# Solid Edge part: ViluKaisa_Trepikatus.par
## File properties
Author: kaisa
Template: Iso Metric Part.par
Last saved by: kaisa
Revision: 6
Application: Solid Edge
Density: 600.000 kg/m^3
Accuracy: 0.990
Username: kaisa
Material: Wood, Mahogany
Face Style: Tan
Fill Style: Wood (Radial)
Virtual Style: Wood (Radial)
Grouping: Non-metals\Woods
LibraryName: Materials
Coef. of Thermal Exp: 0.0
Thermal Conductivity: 0.0
Specific Heat: 0.0
Modulus of Elasticity: 0.0
Poisson's Ratio: 0.428
Yield Stress: 0.0
Ultimate Stress: 0.0
Elongation: 0.0
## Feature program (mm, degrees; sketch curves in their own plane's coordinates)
sketch for "unnamed Protrusion 1" plane through (0, 0, 0) normal (0, 0, 1) x-axis (1, 0, 0)
  line (-20.4133, 35.3589) -> (-20.4133, -35.3589)
  line (-20.4133, -35.3589) -> (20.4133, -35.3589)
  line (20.4133, -35.3589) -> (20.4133, 35.3589)
  line (20.4133, 35.3589) -> (-20.4133, 35.3589)
extrude "unnamed Protrusion 1" add finite 50 along +normal
draft "Draft_1"  Angles1 = 3 deg
chamfer "Chamfer_1" setback 4
thinwall "Thinwall_1"  Thickness = 3 mm
sketch for "unnamed Protrusion 2" #1 plane through (-22.8268, 0, 23.0551) normal (-0.99863, 0, 0.052336) x-axis (0, -1, 0)
  line (0, 0) -> (0, 0)
  line (0, 0) -> (0, 0)
  line (0, 0) -> (0, 0)
  line (0, 0) -> (0, 0)
sketch for "unnamed Protrusion 2" #2 plane through (-22.8268, 0, 23.0551) normal (-0.99863, 0, 0.052336) x-axis (0, -1, 0)
sketch for "unnamed Protrusion 2" #3 plane through (-22.8268, 0, 23.0551) normal (-0.99863, 0, 0.052336) x-axis (0, -1, 0)
sketch for "unnamed Protrusion 2" #4 plane through (-22.8268, 0, 23.0551) normal (-0.99863, 0, 0.052336) x-axis (0, -1, 0)
sketch for "unnamed Protrusion 2" #5 plane through (-22.8268, 0, 23.0551) normal (-0.99863, 0, 0.052336) x-axis (0, -1, 0)
sketch for "unnamed Protrusion 2" #6 plane through (-22.8268, 0, 23.0551) normal (-0.99863, 0, 0.052336) x-axis (0, -1, 0)
sketch for "unnamed Protrusion 2" #7 plane through (-22.8268, 0, 23.0551) normal (-0.99863, 0, 0.052336) x-axis (0, -1, 0)
sketch for "unnamed Protrusion 2" #8 plane through (-22.8268, 0, 23.0551) normal (-0.99863, 0, 0.052336) x-axis (0, -1, 0)
sketch for "unnamed Protrusion 2" #9 plane through (-22.8268, 0, 23.0551) normal (-0.99863, 0, 0.052336) x-axis (0, -1, 0)
sketch for "unnamed Protrusion 2" #10 plane through (-22.8268, 0, 23.0551) normal (-0.99863, 0, 0.052336) x-axis (0, -1, 0)
sketch for "unnamed Protrusion 2" #11 plane through (-22.8268, 0, 23.0551) normal (-0.99863, 0, 0.052336) x-axis (0, -1, 0)
sketch for "unnamed Protrusion 2" #12 plane through (-22.8268, 0, 23.0551) normal (-0.99863, 0, 0.052336) x-axis (0, -1, 0)
sketch for "unnamed Protrusion 2" #13 plane through (-22.8268, 0, 23.0551) normal (-0.99863, 0, 0.052336) x-axis (0, -1, 0)
sketch for "unnamed Protrusion 2" #14 plane through (-22.8268, 0, 23.0551) normal (-0.99863, 0, 0.052336) x-axis (0, -1, 0)
sketch for "unnamed Protrusion 2" #15 plane through (-22.8268, 0, 23.0551) normal (-0.99863, 0, 0.052336) x-axis (0, -1, 0)
extrude "unnamed Protrusion 2" add along -normal
Other named dimensions: "OffsetSurface_1": Distance = 1 mm | "OffsetSurface_2": Distance = 0.1 mm
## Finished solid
Body 1: sheet body, 1 face, 4 edges, 4 vertices.
  Faces by surface: plane 1
  Edges by curve: line 4
Body 2: sheet body, 1 face, 4 edges, 4 vertices.
  Faces by surface: plane 1
  Edges by curve: line 4
Body 3: solid body, 775 faces, 2241 edges, 1490 vertices, 12 separate solids.
  Faces by surface: swept 391, plane 302, cylinder 82
  Edges by curve: line 1295, spline 744, circle 164, intersection 38
Bounding box of the edges (mm; curved faces can reach further): 47.066 x 75.959 x 50.000, from (-24.0323, -37.9793, 0) to (23.0337, 37.9793, 50).
Cylindrical faces by radius (mm): R0.0759 x1, R0.0771 x2, R0.0831 x1, R0.0975 x1, R0.1063 x1, R0.1142 x1, R0.1214 x1, R0.1384 x1, R0.1406 x1, R0.1437 x1, R0.1473 x1, R0.1579 x1, R0.1651 x1, R0.1656 x1, R0.1895 x1, R0.1954 x1, R0.2028 x1, R0.204 x1, R0.2082 x1, R0.2088 x1, R0.2157 x1, R0.2217 x1, R0.2575 x1, R0.2582 x1, R0.2663 x1, R0.2747 x1, R0.2906 x1, R0.2915 x1, R0.2988 x1, R0.3017 x1, R0.3364 x1, R0.3369 x1, R0.3513 x1, R0.3599 x1, R0.3693 x1, R0.3805 x1, R0.3907 x1, R0.4041 x1, R0.4165 x1, R0.427 x1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
Planar faces by outward normal: +y 3, +z 1, -y 10, -z 2, oblique 286
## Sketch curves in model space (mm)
line (20.4133, -35.3589, 0) -> (20.4133, 35.3589, 0)
line (20.4133, 35.3589, 0) -> (-20.4133, 35.3589, 0)
line (-20.4133, 35.3589, 0) -> (-20.4133, -35.3589, 0)
line (-20.4133, -35.3589, 0) -> (20.4133, -35.3589, 0)
spline (-22.2942, -23.682, 33.2179) -> (-22.292, -23.7228, 33.2594) -> (-22.2898, -23.7928, 33.3009)
spline (-22.2991, -23.5267, 33.1238) -> (-22.2964, -23.6272, 33.175) -> (-22.2942, -23.682, 33.2179)
spline (-22.3037, -23.4103, 33.0352) -> (-22.3014, -23.4685, 33.0795) -> (-22.2991, -23.5267, 33.1238)
spline (-22.313, -23.0943, 32.858) -> (-22.3094, -23.2232, 32.9279) -> (-22.3037, -23.4103, 33.0352)
spline (-22.322, -22.8836, 32.6864) -> (-22.3179, -22.9963, 32.7657) -> (-22.313, -23.0943, 32.858)
spline (-22.3238, -22.8226, 32.6532) -> (-22.3233, -22.8531, 32.6615) -> (-22.322, -22.8836, 32.6864)
spline (-22.3284, -22.6674, 32.5646) -> (-22.3261, -22.7448, 32.6094) -> (-22.3238, -22.8226, 32.6532)
spline (-22.3307, -22.5732, 32.5203) -> (-22.3296, -22.6099, 32.5424) -> (-22.3284, -22.6674, 32.5646)
spline (-22.2985, -22.4456, 33.1348) -> (-22.3306, -22.1165, 32.5224) -> (-22.3307, -22.5732, 32.5203)
spline (-22.2933, -22.4844, 33.2345) -> (-22.2959, -22.465, 33.1847) -> (-22.2985, -22.4456, 33.1348)
spline (-22.2863, -22.6341, 33.3674) -> (-22.2912, -22.5219, 33.2739) -> (-22.2933, -22.4844, 33.2345)
spline (-22.2759, -22.806, 33.5667) -> (-22.2797, -22.6951, 33.494) -> (-22.2863, -22.6341, 33.3674)
spline (-22.2631, -23.0721, 33.8103) -> (-22.2685, -22.989, 33.7072) -> (-22.2759, -22.806, 33.5667)
spline (-22.2428, -24.0257, 34.1978) -> (-22.2503, -23.5272, 34.0542) -> (-22.2631, -23.0721, 33.8103)
spline (-22.244, -24.1421, 34.1757) -> (-22.2434, -24.0839, 34.1868) -> (-22.2428, -24.0257, 34.1978)
spline (-22.2434, -24.2142, 34.1868) -> (-22.2437, -24.1781, 34.1812) -> (-22.244, -24.1421, 34.1757)
spline (-22.2454, -24.2918, 34.148) -> (-22.2444, -24.253, 34.1674) -> (-22.2434, -24.2142, 34.1868)
spline (-22.2448, -24.4027, 34.1591) -> (-22.2451, -24.3472, 34.1535) -> (-22.2454, -24.2918, 34.148)
spline (-22.2454, -24.5025, 34.148) -> (-22.2451, -24.4526, 34.1535) -> (-22.2448, -24.4027, 34.1591)
spline (-22.244, -24.5468, 34.1757) -> (-22.2447, -24.5246, 34.1618) -> (-22.2454, -24.5025, 34.148)
spline (-22.273, -24.07, 33.622) -> (-22.2594, -24.3533, 33.8818) -> (-22.244, -24.5468, 34.1757)
spline (-22.2898, -23.7928, 33.3009) -> (-22.2799, -23.9314, 33.4892) -> (-22.273, -24.07, 33.622)
spline (-22.2976, -25.5558, 33.1514) -> (-22.2934, -25.6147, 33.2317) -> (-22.2901, -25.6778, 33.2954)
spline (-22.2988, -25.5004, 33.1293) -> (-22.2982, -25.5281, 33.1404) -> (-22.2976, -25.5558, 33.1514)
spline (-22.3127, -25.1234, 32.8636) -> (-22.3049, -25.384, 33.013) -> (-22.2988, -25.5004, 33.1293)
spline (-22.3052, -25.0846, 33.0075) -> (-22.31, -25.0936, 32.9148) -> (-22.3127, -25.1234, 32.8636)
spline (-22.2971, -25.1068, 33.1625) -> (-22.3011, -25.0957, 33.085) -> (-22.3052, -25.0846, 33.0075)
spline (-22.2785, -25.1899, 33.5169) -> (-22.2875, -25.1019, 33.345) -> (-22.2971, -25.1068, 33.1625)
spline (-22.2611, -25.3063, 33.849) -> (-22.2698, -25.2472, 33.6836) -> (-22.2785, -25.1899, 33.5169)
spline (-22.2016, -24.1865, 34.984) -> (-22.2122, -25.0544, 34.7816) -> (-22.2611, -25.3063, 33.849)
spline (-22.2016, -24.1754, 34.984) -> (-22.2016, -24.1809, 34.984) -> (-22.2016, -24.1865, 34.984)
spline (-22.1993, -24.0312, 35.0283) -> (-22.1996, -24.0897, 35.023) -> (-22.2016, -24.1754, 34.984)
spline (-22.2564, -22.2405, 33.9376) -> (-22.2213, -23.0626, 34.6077) -> (-22.1993, -24.0312, 35.0283)
spline (-22.2814, -21.8303, 33.4615) -> (-22.2679, -22.0162, 33.7191) -> (-22.2564, -22.2405, 33.9376)
spline (-22.2852, -21.7748, 33.3895) -> (-22.2833, -21.8025, 33.4255) -> (-22.2814, -21.8303, 33.4615)
spline (-22.3119, -21.5531, 32.8802) -> (-22.2991, -21.5869, 33.1233) -> (-22.2852, -21.7748, 33.3895)
spline (-22.3272, -21.4533, 32.5867) -> (-22.3175, -21.4447, 32.7719) -> (-22.3119, -21.5531, 32.8802)
spline (-22.3435, -21.4921, 32.2767) -> (-22.3356, -21.4457, 32.4271) -> (-22.3272, -21.4533, 32.5867)
spline (-22.3557, -21.5531, 32.0442) -> (-22.3496, -21.5226, 32.1604) -> (-22.3435, -21.4921, 32.2767)
spline (-22.3551, -22.7727, 32.0552) -> (-22.3706, -22.0696, 31.7594) -> (-22.3557, -21.5531, 32.0442)
spline (-22.3533, -22.8115, 32.0885) -> (-22.3542, -22.7921, 32.0719) -> (-22.3551, -22.7727, 32.0552)
spline (-22.3162, -23.6321, 32.7971) -> (-22.3368, -23.2574, 32.4052) -> (-22.3533, -22.8115, 32.0885)
spline (-22.3168, -23.7429, 32.786) -> (-22.3165, -23.6875, 32.7916) -> (-22.3162, -23.6321, 32.7971)
spline (-22.3139, -23.7984, 32.8414) -> (-22.3153, -23.7707, 32.8137) -> (-22.3168, -23.7429, 32.786)
spline (-22.3069, -23.9869, 32.9743) -> (-22.3104, -23.9037, 32.9078) -> (-22.3139, -23.7984, 32.8414)
spline (-22.3052, -24.009, 33.0075) -> (-22.3061, -23.998, 32.9909) -> (-22.3069, -23.9869, 32.9743)
spline (-22.2997, -24.1255, 33.1127) -> (-22.3026, -24.0735, 33.0559) -> (-22.3052, -24.009, 33.0075)
spline (-22.2924, -24.1975, 33.2511) -> (-22.2952, -24.1574, 33.1985) -> (-22.2997, -24.1255, 33.1127)
spline (-22.2863, -24.4193, 33.3674) -> (-22.2904, -24.316, 33.2903) -> (-22.2924, -24.1975, 33.2511)
spline (-22.2884, -24.4415, 33.3286) -> (-22.287, -24.4366, 33.3542) -> (-22.2863, -24.4193, 33.3674)
spline (-22.3029, -24.4082, 33.0518) -> (-22.2956, -24.4249, 33.1902) -> (-22.2884, -24.4415, 33.3286)
spline (-22.3058, -24.4193, 32.9964) -> (-22.3042, -24.4117, 33.0262) -> (-22.3029, -24.4082, 33.0518)
spline (-22.3156, -24.4359, 32.8082) -> (-22.3101, -24.429, 32.9141) -> (-22.3058, -24.4193, 32.9964)
spline (-22.3185, -24.4637, 32.7528) -> (-22.3172, -24.4581, 32.7784) -> (-22.3156, -24.4359, 32.8082)
spline (-22.3243, -24.4415, 32.6421) -> (-22.3214, -24.4526, 32.6975) -> (-22.3185, -24.4637, 32.7528)
spline (-22.3391, -24.5524, 32.3597) -> (-22.3322, -24.4791, 32.4919) -> (-22.3243, -24.4415, 32.6421)
spline (-22.3429, -24.5912, 32.2878) -> (-22.3411, -24.5635, 32.3217) -> (-22.3391, -24.5524, 32.3597)
spline (-22.3383, -25.4228, 32.3764) -> (-22.3481, -24.9709, 32.1882) -> (-22.3429, -24.5912, 32.2878)
spline (-22.3351, -25.4339, 32.4373) -> (-22.3367, -25.4283, 32.4068) -> (-22.3383, -25.4228, 32.3764)
spline (-22.3325, -25.5669, 32.4871) -> (-22.334, -25.5045, 32.458) -> (-22.3351, -25.4339, 32.4373)
spline (-22.3145, -26.0215, 32.8303) -> (-22.325, -25.8013, 32.6289) -> (-22.3325, -25.5669, 32.4871)
spline (-22.3101, -26.077, 32.9134) -> (-22.3123, -26.0492, 32.8719) -> (-22.3145, -26.0215, 32.8303)
spline (-22.3037, -26.21, 33.0352) -> (-22.3066, -26.1643, 32.9805) -> (-22.3101, -26.077, 32.9134)
spline (-22.2985, -26.3209, 33.1348) -> (-22.3011, -26.253, 33.085) -> (-22.3037, -26.21, 33.0352)
spline (-22.2947, -26.3653, 33.2068) -> (-22.2966, -26.3431, 33.1708) -> (-22.2985, -26.3209, 33.1348)
spline (-22.2863, -26.3874, 33.3674) -> (-22.2905, -26.3763, 33.2871) -> (-22.2947, -26.3653, 33.2068)
spline (-22.2582, -26.3763, 33.9044) -> (-22.2726, -26.4861, 33.6302) -> (-22.2863, -26.3874, 33.3674)
spline (-22.2857, -25.7665, 33.3784) -> (-22.2729, -26.0672, 33.6234) -> (-22.2582, -26.3763, 33.9044)
spline (-22.2901, -25.6778, 33.2954) -> (-22.2879, -25.7225, 33.3365) -> (-22.2857, -25.7665, 33.3784)
spline (-22.2608, -17.3763, 33.8546) -> (-22.2456, -17.7577, 34.1452) -> (-22.2245, -18.1359, 34.5466)
spline (-22.2672, -17.2599, 33.7328) -> (-22.2651, -17.3223, 33.7729) -> (-22.2608, -17.3763, 33.8546)
spline (-22.2759, -16.9883, 33.5667) -> (-22.27, -17.1615, 33.6788) -> (-22.2672, -17.2599, 33.7328)
spline (-22.2759, -16.9772, 33.5667) -> (-22.2759, -16.9827, 33.5667) -> (-22.2759, -16.9883, 33.5667)
spline (-22.2751, -16.9548, 33.5816) -> (-22.2755, -16.966, 33.5741) -> (-22.2759, -16.9772, 33.5667)
spline (-22.2759, -16.9328, 33.5667) -> (-22.2755, -16.949, 33.5741) -> (-22.2751, -16.9548, 33.5816)
spline (-22.2776, -16.8718, 33.5335) -> (-22.2767, -16.9086, 33.5501) -> (-22.2759, -16.9328, 33.5667)
spline (-22.3014, -17.0548, 33.0795) -> (-22.299, -16.8163, 33.1251) -> (-22.2776, -16.8718, 33.5335)
spline (-22.2689, -17.8531, 33.6996) -> (-22.2856, -17.4604, 33.3813) -> (-22.3014, -17.0548, 33.0795)
spline (-22.239, -18.7623, 34.2698) -> (-22.246, -18.3096, 34.1359) -> (-22.2689, -17.8531, 33.6996)
spline (-22.2466, -18.7402, 34.1259) -> (-22.2428, -18.7513, 34.1978) -> (-22.239, -18.7623, 34.2698)
spline (-22.2512, -18.7623, 34.0373) -> (-22.2481, -18.745, 34.0961) -> (-22.2466, -18.7402, 34.1259)
spline (-22.2538, -18.7402, 33.9874) -> (-22.2525, -18.7513, 34.0124) -> (-22.2512, -18.7623, 34.0373)
spline (-22.2599, -18.7513, 33.8712) -> (-22.2569, -18.7457, 33.9293) -> (-22.2538, -18.7402, 33.9874)
spline (-22.266, -18.6958, 33.7549) -> (-22.263, -18.7235, 33.8131) -> (-22.2599, -18.7513, 33.8712)
spline (-22.2709, -18.7402, 33.6608) -> (-22.2682, -18.7076, 33.7141) -> (-22.266, -18.6958, 33.7549)
spline (-22.2733, -18.7513, 33.6165) -> (-22.2721, -18.7457, 33.6387) -> (-22.2709, -18.7402, 33.6608)
spline (-22.2849, -18.6127, 33.3951) -> (-22.278, -18.639, 33.5268) -> (-22.2733, -18.7513, 33.6165)
spline (-22.2933, -18.5794, 33.2345) -> (-22.2897, -18.5815, 33.3024) -> (-22.2849, -18.6127, 33.3951)
spline (-22.3066, -18.3798, 32.9798) -> (-22.3, -18.4796, 33.1072) -> (-22.2933, -18.5794, 33.2345)
spline (-22.322, -18.2246, 32.6864) -> (-22.3146, -18.3063, 32.8277) -> (-22.3066, -18.3798, 32.9798)
spline (-22.322, -18.1802, 32.6864) -> (-22.322, -18.2024, 32.6864) -> (-22.322, -18.2246, 32.6864)
spline (-22.3226, -18.158, 32.6753) -> (-22.3223, -18.1691, 32.6809) -> (-22.322, -18.1802, 32.6864)
spline (-22.3275, -17.7811, 32.5812) -> (-22.3287, -17.9826, 32.5592) -> (-22.3226, -18.158, 32.6753)
spline (-22.3281, -17.6923, 32.5701) -> (-22.3278, -17.7367, 32.5757) -> (-22.3275, -17.7811, 32.5812)
spline (-22.3275, -17.6702, 32.5812) -> (-22.3279, -17.675, 32.5736) -> (-22.3281, -17.6923, 32.5701)
spline (-22.322, -17.526, 32.6864) -> (-22.3236, -17.5898, 32.6566) -> (-22.3275, -17.6702, 32.5812)
spline (-22.3258, -17.3264, 32.6144) -> (-22.3236, -17.4278, 32.6554) -> (-22.322, -17.526, 32.6864)
spline (-22.3423, -16.8885, 32.2988) -> (-22.3313, -17.0476, 32.5087) -> (-22.3258, -17.3264, 32.6144)
spline (-22.3658, -18.3077, 31.8504) -> (-22.3759, -17.3439, 31.6579) -> (-22.3423, -16.8885, 32.2988)
spline (-22.3594, -18.5295, 31.9722) -> (-22.3629, -18.3874, 31.9071) -> (-22.3658, -18.3077, 31.8504)
spline (-22.3554, -18.6293, 32.0497) -> (-22.3574, -18.5794, 32.0109) -> (-22.3594, -18.5295, 31.9722)
spline (-22.3458, -18.973, 32.2324) -> (-22.3503, -18.7909, 32.1462) -> (-22.3554, -18.6293, 32.0497)
spline (-22.342, -19.0229, 32.3044) -> (-22.3439, -18.998, 32.2684) -> (-22.3458, -18.973, 32.2324)
spline (-22.3339, -19.411, 32.4594) -> (-22.3393, -19.2221, 32.3563) -> (-22.342, -19.0229, 32.3044)
spline (-22.3327, -19.4332, 32.4815) -> (-22.3333, -19.4221, 32.4705) -> (-22.3339, -19.411, 32.4594)
spline (-22.3316, -19.4886, 32.5037) -> (-22.3323, -19.4671, 32.4905) -> (-22.3327, -19.4332, 32.4815)
spline (-22.3258, -19.6438, 32.6144) -> (-22.3281, -19.5371, 32.5694) -> (-22.3316, -19.4886, 32.5037)
spline (-22.3188, -19.6993, 32.7473) -> (-22.3234, -19.6695, 32.6601) -> (-22.3258, -19.6438, 32.6144)
spline (-22.3177, -19.8212, 32.7694) -> (-22.3182, -19.7603, 32.7584) -> (-22.3188, -19.6993, 32.7473)
spline (-22.3066, -20.0319, 32.9798) -> (-22.3143, -19.8767, 32.8331) -> (-22.3177, -19.8212, 32.7694)
spline (-22.2997, -20.1816, 33.1127) -> (-22.3026, -20.1539, 33.0573) -> (-22.3066, -20.0319, 32.9798)
spline (-22.2971, -20.3313, 33.1625) -> (-22.2984, -20.2897, 33.1376) -> (-22.2997, -20.1816, 33.1127)
spline (-22.2933, -20.3923, 33.2345) -> (-22.2952, -20.3618, 33.1985) -> (-22.2971, -20.3313, 33.1625)
spline (-22.2898, -20.5032, 33.3009) -> (-22.2915, -20.4477, 33.2677) -> (-22.2933, -20.3923, 33.2345)
spline (-22.2776, -20.6917, 33.5335) -> (-22.2808, -20.6411, 33.4733) -> (-22.2898, -20.5032, 33.3009)
spline (-22.2733, -20.8746, 33.6165) -> (-22.2757, -20.8122, 33.5708) -> (-22.2776, -20.6917, 33.5335)
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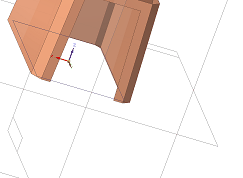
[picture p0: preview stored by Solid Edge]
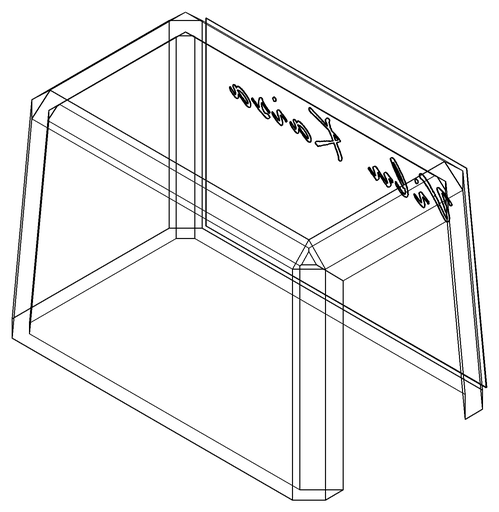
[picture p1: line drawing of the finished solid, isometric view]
